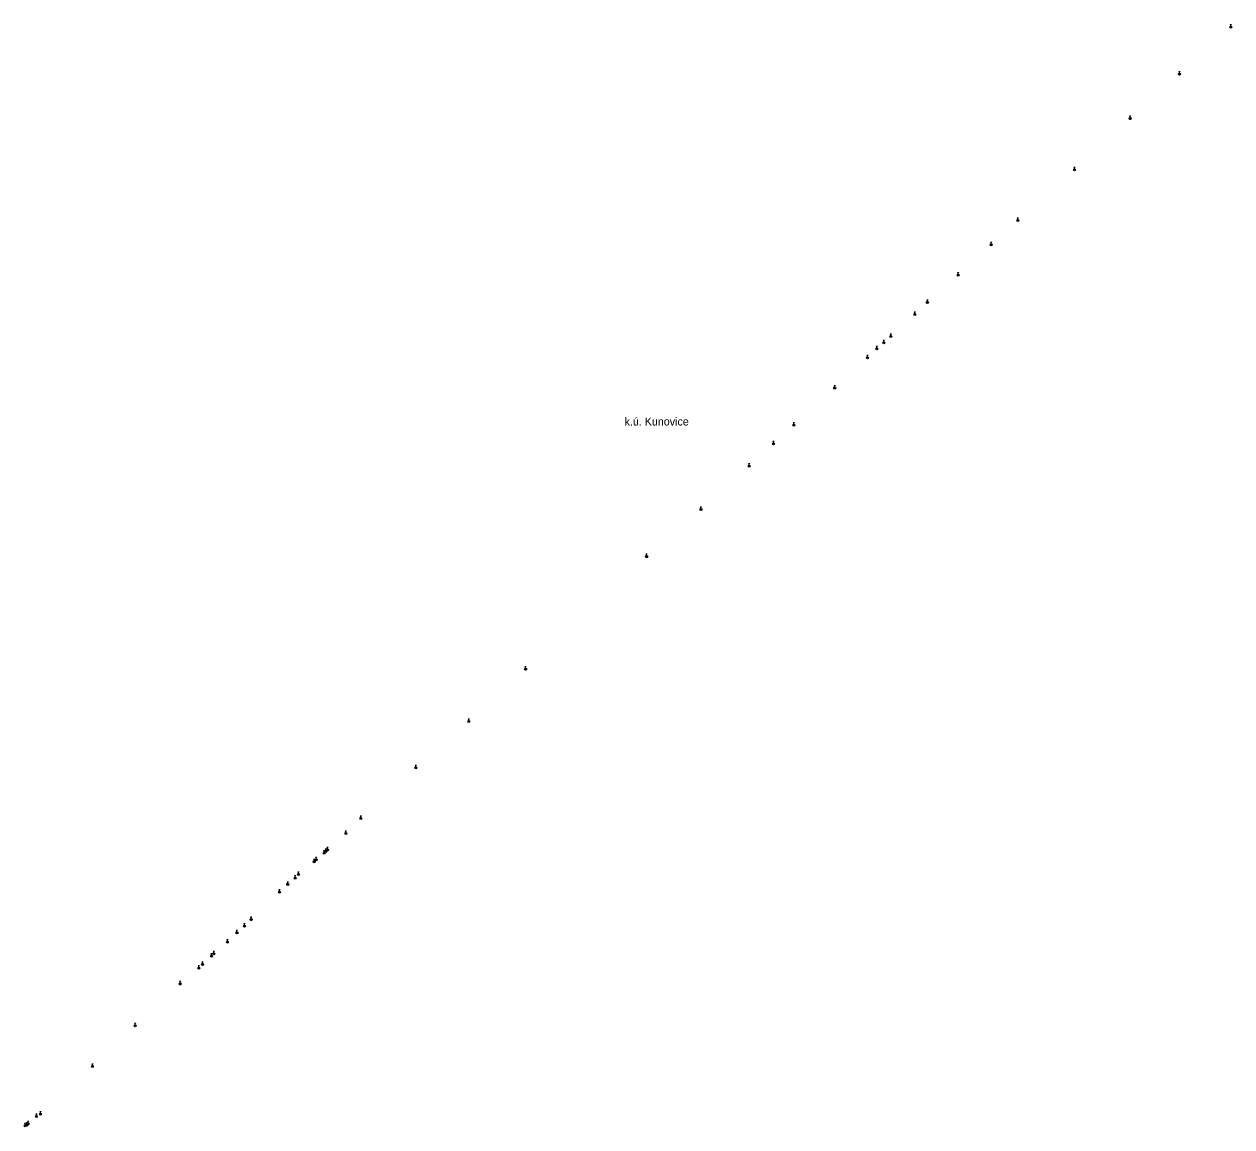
# Model space of a CAD drawing. Extents: x -540161 to -537510, y -1183993 to -1180459.
# Drawn here: x -539812.4 to -539359.7, y -1183114.6 to -1182701 of the extents above; entities that cross this region are included whole.
import ezdxf

# ---------------------------------------------------------------- set-up
doc = ezdxf.new("R2010")
doc.units = 0
doc.layers.add('NÁZEV_K_Ú', color=7, linetype='Continuous')
doc.layers.add('ZN_BP', color=7, linetype='Continuous')

msp = doc.modelspace()

# ---------------------------------------------------------------- linework, layer by layer
at = {"layer": 'ZN_BP'}
for p, q in [((-539360.06, -1182701.785), (-539360.06, -1182701.035)), ((-539360.325, -1182702.424), (-539359.796, -1182701.896)), ((-539359.796, -1182702.428), (-539360.325, -1182701.896)), ((-539379.555, -1182720.004), (-539379.026, -1182719.476)), ((-539379.026, -1182720.008), (-539379.555, -1182719.476)), ((-539379.29, -1182719.365), (-539379.29, -1182718.615)), ((-539398.075, -1182736.744), (-539397.546, -1182736.216)), ((-539397.546, -1182736.748), (-539398.075, -1182736.216)), ((-539397.81, -1182736.105), (-539397.81, -1182735.355)), ((-539418.945, -1182755.984), (-539418.416, -1182755.456)), ((-539418.416, -1182755.988), (-539418.945, -1182755.456)), ((-539418.68, -1182755.345), (-539418.68, -1182754.595)), ((-539439.88, -1182774.265), (-539439.88, -1182773.515)), ((-539440.145, -1182774.904), (-539439.616, -1182774.376)), ((-539439.616, -1182774.908), (-539440.145, -1182774.376)), ((-539449.88, -1182783.385), (-539449.88, -1182782.635)), ((-539450.145, -1182784.024), (-539449.616, -1182783.496)), ((-539449.616, -1182784.028), (-539450.145, -1182783.496)), ((-539462.515, -1182795.444), (-539461.986, -1182794.916)), ((-539461.986, -1182795.448), (-539462.515, -1182794.916)), ((-539462.25, -1182794.805), (-539462.25, -1182794.055)), ((-539474.095, -1182805.664), (-539473.566, -1182805.136)), ((-539473.566, -1182805.668), (-539474.095, -1182805.136)), ((-539473.83, -1182805.025), (-539473.83, -1182804.275)), ((-539478.795, -1182810.164), (-539478.266, -1182809.636)), ((-539478.266, -1182810.168), (-539478.795, -1182809.636)), ((-539478.53, -1182809.525), (-539478.53, -1182808.775)), ((-539490.15, -1182820.185), (-539490.15, -1182819.435)), ((-539487.795, -1182818.444), (-539487.266, -1182817.916)), ((-539487.266, -1182818.448), (-539487.795, -1182817.916)), ((-539487.53, -1182817.805), (-539487.53, -1182817.055)), ((-539493.035, -1182823.084), (-539492.506, -1182822.556)), ((-539492.506, -1182823.088), (-539493.035, -1182822.556)), ((-539492.77, -1182822.445), (-539492.77, -1182821.695)), ((-539490.415, -1182820.824), (-539489.886, -1182820.296)), ((-539489.886, -1182820.828), (-539490.415, -1182820.296)), ((-539496.575, -1182826.444), (-539496.046, -1182825.916)), ((-539496.046, -1182826.448), (-539496.575, -1182825.916)), ((-539496.31, -1182825.805), (-539496.31, -1182825.055)), ((-539508.835, -1182837.774), (-539508.306, -1182837.246)), ((-539508.306, -1182837.778), (-539508.835, -1182837.246)), ((-539508.57, -1182837.135), (-539508.57, -1182836.385)), ((-539523.86, -1182851.055), (-539523.86, -1182850.305)), ((-539524.125, -1182851.694), (-539523.596, -1182851.166)), ((-539523.596, -1182851.698), (-539524.125, -1182851.166)), ((-539531.745, -1182858.704), (-539531.216, -1182858.176)), ((-539531.216, -1182858.708), (-539531.745, -1182858.176)), ((-539531.48, -1182858.065), (-539531.48, -1182857.315)), ((-539540.935, -1182867.064), (-539540.406, -1182866.536)), ((-539540.406, -1182867.068), (-539540.935, -1182866.536)), ((-539540.67, -1182866.425), (-539540.67, -1182865.675)), ((-539558.955, -1182883.304), (-539558.426, -1182882.776)), ((-539558.426, -1182883.308), (-539558.955, -1182882.776)), ((-539558.69, -1182882.665), (-539558.69, -1182881.915)), ((-539579.325, -1182901.034), (-539578.796, -1182900.506)), ((-539578.796, -1182901.038), (-539579.325, -1182900.506)), ((-539579.06, -1182900.395), (-539579.06, -1182899.645)), ((-539624.695, -1182943.234), (-539624.166, -1182942.706)), ((-539624.166, -1182943.238), (-539624.695, -1182942.706)), ((-539624.43, -1182942.595), (-539624.43, -1182941.845)), ((-539646.025, -1182962.824), (-539645.496, -1182962.296)), ((-539645.496, -1182962.828), (-539646.025, -1182962.296)), ((-539645.76, -1182962.185), (-539645.76, -1182961.435)), ((-539665.845, -1182980.244), (-539665.316, -1182979.716)), ((-539665.316, -1182980.248), (-539665.845, -1182979.716)), ((-539665.58, -1182979.605), (-539665.58, -1182978.855)), ((-539686.435, -1182999.244), (-539685.906, -1182998.716)), ((-539685.906, -1182999.248), (-539686.435, -1182998.716)), ((-539686.17, -1182998.605), (-539686.17, -1182997.855)), ((-539692.095, -1183004.884), (-539691.566, -1183004.356)), ((-539691.566, -1183004.888), (-539692.095, -1183004.356)), ((-539691.83, -1183004.245), (-539691.83, -1183003.495)), ((-539703.69, -1183014.795), (-539703.69, -1183014.045)), ((-539702.93, -1183014.045), (-539702.93, -1183013.295)), ((-539700.245, -1183012.234), (-539699.716, -1183011.706)), ((-539699.716, -1183012.238), (-539700.245, -1183011.706)), ((-539699.98, -1183011.595), (-539699.98, -1183010.845)), ((-539699.565, -1183011.594), (-539699.036, -1183011.066)), ((-539699.036, -1183011.598), (-539699.565, -1183011.066)), ((-539699.3, -1183010.955), (-539699.3, -1183010.205)), ((-539699.025, -1183011.044), (-539698.496, -1183010.516)), ((-539698.496, -1183011.048), (-539699.025, -1183010.516)), ((-539698.76, -1183010.405), (-539698.76, -1183009.655)), ((-539703.955, -1183015.434), (-539703.426, -1183014.906)), ((-539703.426, -1183015.438), (-539703.955, -1183014.906)), ((-539703.195, -1183014.684), (-539702.666, -1183014.156)), ((-539702.666, -1183014.688), (-539703.195, -1183014.156)), ((-539713.63, -1183023.305), (-539713.63, -1183022.555)), ((-539711.115, -1183021.654), (-539710.586, -1183021.126)), ((-539710.586, -1183021.658), (-539711.115, -1183021.126)), ((-539710.85, -1183021.015), (-539710.85, -1183020.265)), ((-539709.845, -1183020.284), (-539709.316, -1183019.756)), ((-539709.316, -1183020.288), (-539709.845, -1183019.756)), ((-539709.58, -1183019.645), (-539709.58, -1183018.895)), ((-539716.955, -1183026.844), (-539716.426, -1183026.316)), ((-539716.426, -1183026.848), (-539716.955, -1183026.316)), ((-539716.69, -1183026.205), (-539716.69, -1183025.455)), ((-539713.895, -1183023.944), (-539713.366, -1183023.416)), ((-539713.366, -1183023.948), (-539713.895, -1183023.416)), ((-539727.555, -1183037.174), (-539727.026, -1183036.646)), ((-539727.026, -1183037.178), (-539727.555, -1183036.646)), ((-539727.29, -1183036.535), (-539727.29, -1183035.785)), ((-539732.64, -1183041.465), (-539732.64, -1183040.715)), ((-539730.125, -1183039.634), (-539729.596, -1183039.106)), ((-539729.596, -1183039.638), (-539730.125, -1183039.106)), ((-539729.86, -1183038.995), (-539729.86, -1183038.245)), ((-539736.415, -1183045.584), (-539735.886, -1183045.056)), ((-539735.886, -1183045.588), (-539736.415, -1183045.056)), ((-539736.15, -1183044.945), (-539736.15, -1183044.195)), ((-539732.905, -1183042.104), (-539732.376, -1183041.576)), ((-539732.376, -1183042.108), (-539732.905, -1183041.576)), ((-539742.495, -1183050.854), (-539741.966, -1183050.326)), ((-539741.966, -1183050.858), (-539742.495, -1183050.326)), ((-539742.23, -1183050.215), (-539742.23, -1183049.465)), ((-539741.545, -1183050.034), (-539741.016, -1183049.506)), ((-539741.016, -1183050.038), (-539741.545, -1183049.506)), ((-539741.28, -1183049.395), (-539741.28, -1183048.645)), ((-539747.235, -1183055.334), (-539746.706, -1183054.806)), ((-539746.706, -1183055.338), (-539747.235, -1183054.806)), ((-539746.97, -1183054.695), (-539746.97, -1183053.945)), ((-539745.855, -1183053.954), (-539745.326, -1183053.426)), ((-539745.326, -1183053.958), (-539745.855, -1183053.426)), ((-539745.59, -1183053.315), (-539745.59, -1183052.565)), ((-539754.245, -1183061.304), (-539753.716, -1183060.776)), ((-539753.716, -1183061.308), (-539754.245, -1183060.776)), ((-539753.98, -1183060.665), (-539753.98, -1183059.915)), ((-539771.105, -1183076.994), (-539770.576, -1183076.466)), ((-539770.576, -1183076.998), (-539771.105, -1183076.466)), ((-539770.84, -1183076.355), (-539770.84, -1183075.605)), ((-539786.77, -1183091.625), (-539786.77, -1183090.875)), ((-539787.035, -1183092.264), (-539786.506, -1183091.736)), ((-539786.506, -1183092.268), (-539787.035, -1183091.736)), ((-539806.34, -1183109.485), (-539806.34, -1183108.735)), ((-539812.05, -1183113.885), (-539812.05, -1183113.135)), ((-539811.665, -1183114.204), (-539811.136, -1183113.676)), ((-539811.136, -1183114.208), (-539811.665, -1183113.676)), ((-539811.4, -1183113.565), (-539811.4, -1183112.815)), ((-539811.185, -1183113.764), (-539810.656, -1183113.236)), ((-539810.656, -1183113.768), (-539811.185, -1183113.236)), ((-539810.92, -1183113.125), (-539810.92, -1183112.375)), ((-539808.075, -1183111.024), (-539807.546, -1183110.496)), ((-539807.546, -1183111.028), (-539808.075, -1183110.496)), ((-539807.81, -1183110.385), (-539807.81, -1183109.635)), ((-539806.605, -1183110.124), (-539806.076, -1183109.596)), ((-539806.076, -1183110.128), (-539806.605, -1183109.596)), ((-539812.315, -1183114.524), (-539811.786, -1183113.996)), ((-539811.786, -1183114.528), (-539812.315, -1183113.996))]:
    msp.add_line(p, q, dxfattribs=at)
for points in [[(-539360.185, -1182701.285), (-539360.06, -1182701.035), (-539359.935, -1182701.285)], [(-539379.415, -1182718.865), (-539379.29, -1182718.615), (-539379.165, -1182718.865)], [(-539397.935, -1182735.605), (-539397.81, -1182735.355), (-539397.685, -1182735.605)], [(-539418.805, -1182754.845), (-539418.68, -1182754.595), (-539418.555, -1182754.845)], [(-539440.005, -1182773.765), (-539439.88, -1182773.515), (-539439.755, -1182773.765)], [(-539450.005, -1182782.885), (-539449.88, -1182782.635), (-539449.755, -1182782.885)], [(-539462.375, -1182794.305), (-539462.25, -1182794.055), (-539462.125, -1182794.305)], [(-539473.955, -1182804.525), (-539473.83, -1182804.275), (-539473.705, -1182804.525)], [(-539478.655, -1182809.025), (-539478.53, -1182808.775), (-539478.405, -1182809.025)], [(-539490.275, -1182819.685), (-539490.15, -1182819.435), (-539490.025, -1182819.685)], [(-539487.655, -1182817.305), (-539487.53, -1182817.055), (-539487.405, -1182817.305)], [(-539492.895, -1182821.945), (-539492.77, -1182821.695), (-539492.645, -1182821.945)], [(-539496.435, -1182825.305), (-539496.31, -1182825.055), (-539496.185, -1182825.305)], [(-539508.695, -1182836.635), (-539508.57, -1182836.385), (-539508.445, -1182836.635)], [(-539523.985, -1182850.555), (-539523.86, -1182850.305), (-539523.735, -1182850.555)], [(-539531.605, -1182857.565), (-539531.48, -1182857.315), (-539531.355, -1182857.565)], [(-539540.795, -1182865.925), (-539540.67, -1182865.675), (-539540.545, -1182865.925)], [(-539558.815, -1182882.165), (-539558.69, -1182881.915), (-539558.565, -1182882.165)], [(-539579.185, -1182899.895), (-539579.06, -1182899.645), (-539578.935, -1182899.895)], [(-539624.555, -1182942.095), (-539624.43, -1182941.845), (-539624.305, -1182942.095)], [(-539645.885, -1182961.685), (-539645.76, -1182961.435), (-539645.635, -1182961.685)], [(-539665.705, -1182979.105), (-539665.58, -1182978.855), (-539665.455, -1182979.105)], [(-539686.295, -1182998.105), (-539686.17, -1182997.855), (-539686.045, -1182998.105)], [(-539691.955, -1183003.745), (-539691.83, -1183003.495), (-539691.705, -1183003.745)], [(-539703.815, -1183014.295), (-539703.69, -1183014.045), (-539703.565, -1183014.295)], [(-539703.055, -1183013.545), (-539702.93, -1183013.295), (-539702.805, -1183013.545)], [(-539700.105, -1183011.095), (-539699.98, -1183010.845), (-539699.855, -1183011.095)], [(-539699.425, -1183010.455), (-539699.3, -1183010.205), (-539699.175, -1183010.455)], [(-539698.885, -1183009.905), (-539698.76, -1183009.655), (-539698.635, -1183009.905)], [(-539713.755, -1183022.805), (-539713.63, -1183022.555), (-539713.505, -1183022.805)], [(-539710.975, -1183020.515), (-539710.85, -1183020.265), (-539710.725, -1183020.515)], [(-539709.705, -1183019.145), (-539709.58, -1183018.895), (-539709.455, -1183019.145)], [(-539716.815, -1183025.705), (-539716.69, -1183025.455), (-539716.565, -1183025.705)], [(-539727.415, -1183036.035), (-539727.29, -1183035.785), (-539727.165, -1183036.035)], [(-539732.765, -1183040.965), (-539732.64, -1183040.715), (-539732.515, -1183040.965)], [(-539729.985, -1183038.495), (-539729.86, -1183038.245), (-539729.735, -1183038.495)], [(-539736.275, -1183044.445), (-539736.15, -1183044.195), (-539736.025, -1183044.445)], [(-539742.355, -1183049.715), (-539742.23, -1183049.465), (-539742.105, -1183049.715)], [(-539741.405, -1183048.895), (-539741.28, -1183048.645), (-539741.155, -1183048.895)], [(-539747.095, -1183054.195), (-539746.97, -1183053.945), (-539746.845, -1183054.195)], [(-539745.715, -1183052.815), (-539745.59, -1183052.565), (-539745.465, -1183052.815)], [(-539754.105, -1183060.165), (-539753.98, -1183059.915), (-539753.855, -1183060.165)], [(-539770.965, -1183075.855), (-539770.84, -1183075.605), (-539770.715, -1183075.855)], [(-539786.895, -1183091.125), (-539786.77, -1183090.875), (-539786.645, -1183091.125)], [(-539806.465, -1183108.985), (-539806.34, -1183108.735), (-539806.215, -1183108.985)], [(-539812.175, -1183113.385), (-539812.05, -1183113.135), (-539811.925, -1183113.385)], [(-539811.525, -1183113.065), (-539811.4, -1183112.815), (-539811.275, -1183113.065)], [(-539811.045, -1183112.625), (-539810.92, -1183112.375), (-539810.795, -1183112.625)], [(-539807.935, -1183109.885), (-539807.81, -1183109.635), (-539807.685, -1183109.885)]]:
    msp.add_lwpolyline(points, dxfattribs=at)
for centre in [(-539360.06, -1182702.16), (-539379.29, -1182719.74), (-539397.81, -1182736.48), (-539418.68, -1182755.72), (-539439.88, -1182774.64), (-539449.88, -1182783.76), (-539462.25, -1182795.18), (-539473.83, -1182805.4), (-539478.53, -1182809.9), (-539487.53, -1182818.18), (-539492.77, -1182822.82), (-539490.15, -1182820.56), (-539496.31, -1182826.18), (-539508.57, -1182837.51), (-539523.86, -1182851.43), (-539531.48, -1182858.44), (-539540.67, -1182866.8), (-539558.69, -1182883.04), (-539579.06, -1182900.77), (-539624.43, -1182942.97), (-539645.76, -1182962.56), (-539665.58, -1182979.98), (-539686.17, -1182998.98), (-539691.83, -1183004.62), (-539702.93, -1183014.42), (-539699.98, -1183011.97), (-539699.3, -1183011.33), (-539698.76, -1183010.78), (-539703.69, -1183015.17), (-539710.85, -1183021.39), (-539709.58, -1183020.02), (-539716.69, -1183026.58), (-539713.63, -1183023.68), (-539727.29, -1183036.91), (-539729.86, -1183039.37), (-539736.15, -1183045.32), (-539732.64, -1183041.84), (-539742.23, -1183050.59), (-539741.28, -1183049.77), (-539746.97, -1183055.07), (-539745.59, -1183053.69), (-539753.98, -1183061.04), (-539770.84, -1183076.73), (-539786.77, -1183092), (-539811.4, -1183113.94), (-539810.92, -1183113.5), (-539807.81, -1183110.76), (-539806.34, -1183109.86), (-539812.05, -1183114.26)]:
    msp.add_circle(centre, 0.375, dxfattribs=at)

# ---------------------------------------------------------------- texts
at = {"layer": 'NÁZEV_K_Ú'}
msp.add_text('k.ú. Kunovice', height=3, dxfattribs=at).set_placement((-539587.358, -1182851.58))

doc.saveas('drawing.dxf')
